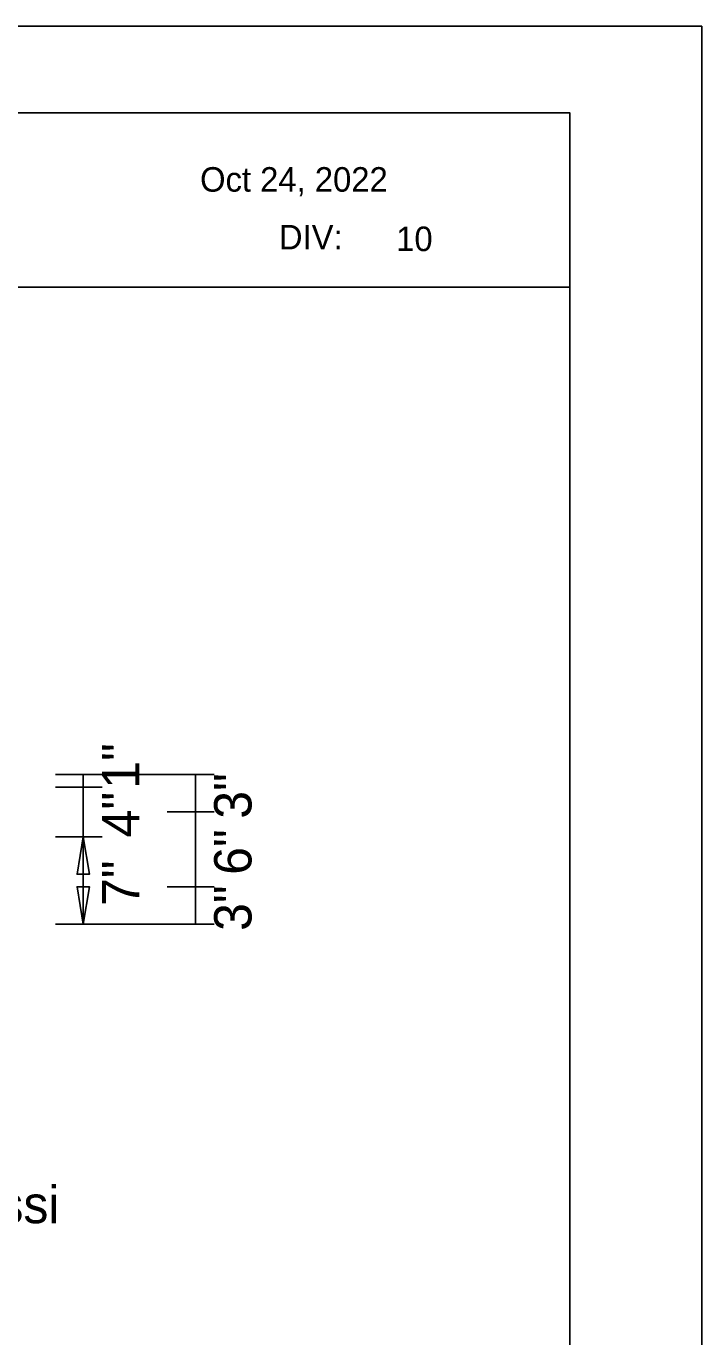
# Model space of a CAD drawing. Extents: x 1708.4 to 1771.6, y 238.3 to 283.4.
# Drawn here: x 1733.01 to 1738.43, y 272.92 to 283.44 of the extents above; entities that cross this region are included whole.
import ezdxf

# ---------------------------------------------------------------- set-up
doc = ezdxf.new("R2010")
doc.units = 0
for name, color, linetype in [('Level 5', 7, 'Continuous'), ('Level 6', 7, 'Continuous'), ('Level 7', 7, 'Continuous'), ('Level 9', 7, 'Continuous')]:
    doc.layers.add(name, color=color, linetype=linetype)

msp = doc.modelspace()

# ---------------------------------------------------------------- linework, layer by layer
at = {"layer": 'Level 5'}
for p, q in [((1733.243, 277.433), (1733.618, 277.433)), ((1733.243, 277.433), (1734.142, 277.433)), ((1733.467, 277.333), (1733.467, 277.433)), ((1734.142, 277.433), (1734.517, 277.433)), ((1734.368, 277.133), (1734.368, 277.433)), ((1733.243, 277.333), (1733.618, 277.333)), ((1733.243, 277.333), (1733.618, 277.333)), ((1733.467, 277.333), (1733.467, 276.933)), ((1734.142, 277.133), (1734.517, 277.133)), ((1734.142, 277.133), (1734.517, 277.133)), ((1734.368, 277.133), (1734.368, 276.533)), ((1733.243, 276.933), (1733.618, 276.933)), ((1733.243, 276.933), (1733.618, 276.933)), ((1733.467, 276.233), (1733.467, 276.933)), ((1734.142, 276.533), (1734.517, 276.533)), ((1734.142, 276.533), (1734.517, 276.533)), ((1734.368, 276.233), (1734.368, 276.533)), ((1733.243, 276.233), (1733.618, 276.233)), ((1733.243, 276.233), (1734.142, 276.233)), ((1734.142, 276.233), (1734.517, 276.233))]:
    msp.add_line(p, q, dxfattribs=at)
for points in [[(1733.467, 276.933), (1733.418, 276.633), (1733.517, 276.633)], [(1733.467, 276.233), (1733.418, 276.533), (1733.517, 276.533)]]:
    msp.add_lwpolyline(points, close=True, dxfattribs=at)
at = {"layer": 'Level 6'}
msp.add_line((1720.21, 281.346), (1737.374, 281.346), dxfattribs=at)
msp.add_lwpolyline([(1709.048, 282.744), (1737.374, 282.744), (1737.374, 263.077), (1709.048, 263.077)], close=True, dxfattribs=at)
at = {"layer": 'Level 9'}
msp.add_lwpolyline([(1708.357, 262.404), (1738.434, 262.404), (1738.434, 283.439), (1708.357, 283.439)], close=True, dxfattribs=at)

# ---------------------------------------------------------------- texts
at = {"layer": 'Level 5'}
for s, p in [(' 1"', (1733.918, 277.208)), ('3"', (1734.818, 277.079)), ('4"', (1733.918, 276.929)), ('6"', (1734.818, 276.629)), ('7"', (1733.918, 276.379)), ('3"', (1734.818, 276.179))]:
    msp.add_text(s, height=0.3, rotation=90, dxfattribs=at).set_placement(p)
msp.add_text('Panel Style: guide_con_street name_c1_2012.ssi', height=0.3, dxfattribs=at).set_placement((1724.467, 273.833))
at = {"layer": 'Level 6'}
msp.add_text('DIV:', height=0.1969, rotation=360, dxfattribs=at).set_placement((1735.038, 281.648))
msp.add_text('10', height=0.1969, dxfattribs=at).set_placement((1735.98, 281.634))
at = {"layer": 'Level 7'}
msp.add_text('Oct 24, 2022', height=0.19685, dxfattribs=at).set_placement((1734.405, 282.111))

doc.saveas('drawing.dxf')
